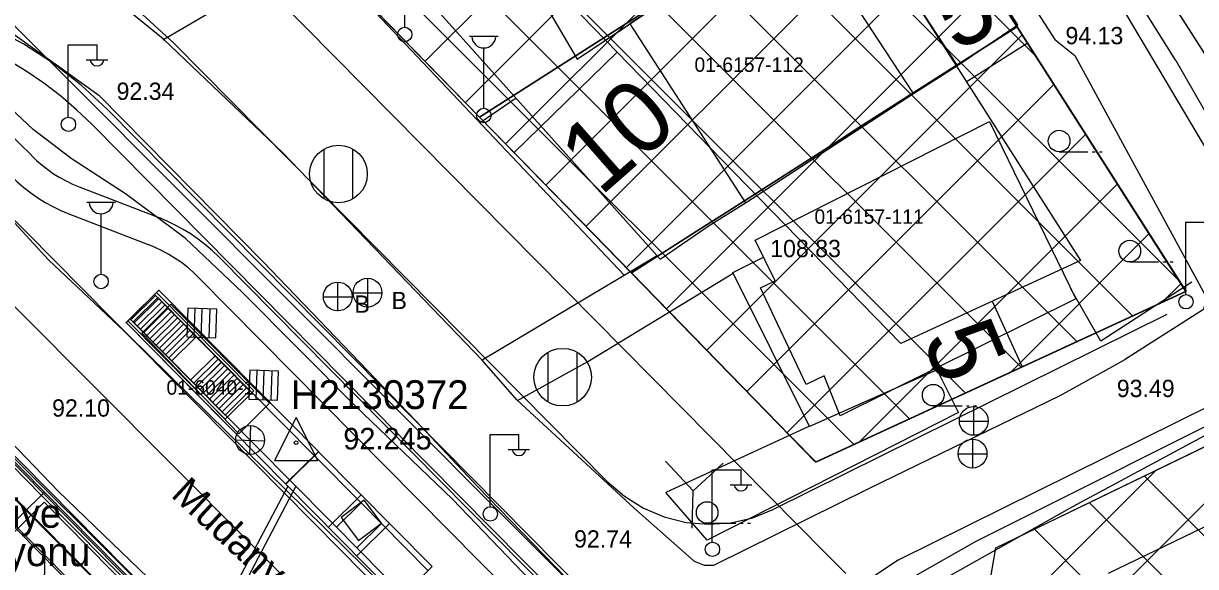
# Model space of a CAD drawing. Extents: x 412225 to 413380, y 4456471 to 4457189.
# Drawn here: x 412847.6 to 412929, y 4456543.1 to 4456580.8 of the extents above; entities that cross this region are included whole.
import ezdxf

# ---------------------------------------------------------------- set-up
doc = ezdxf.new("R2010")
doc.units = 0
for name, color, linetype in [('0_HALİHAZIR', 7, 'Continuous'), ('0_KADASTRO', 7, 'Continuous'), ('Level 20', 7, 'Continuous'), ('Level 28', 7, 'Continuous'), ('Level 34', 7, 'Continuous'), ('Level 62', 7, 'Continuous')]:
    doc.layers.add(name, color=color, linetype=linetype)

msp = doc.modelspace()

# ---------------------------------------------------------------- linework, layer by layer
at = {"layer": '0_HALİHAZIR'}
for p, q in [((412874.076, 4456580.571), (412874.076, 4456584.764)), ((412878.564, 4456579.947), (412880.564, 4456579.947)), ((412850.724, 4456574.359), (412850.724, 4456579.359)), ((412850.724, 4456579.359), (412852.724, 4456579.359)), ((412852.724, 4456578.359), (412852.724, 4456579.359)), ((412879.564, 4456574.947), (412879.564, 4456579.14)), ((412851.964, 4456578.319), (412853.464, 4456578.319)), ((412868.477, 4456568.663), (412868.477, 4456572.123)), ((412870.477, 4456568.663), (412870.477, 4456572.123)), ((412919.494, 4456571.926), (412921.494, 4456571.926)), ((412921.794, 4456571.926), (412921.994, 4456571.926)), ((412922.294, 4456571.926), (412922.494, 4456571.926)), ((412852.002, 4456568.427), (412854.002, 4456568.427)), ((412853.002, 4456563.427), (412853.002, 4456567.62)), ((412928.294, 4456562.045), (412928.294, 4456567.045)), ((412928.294, 4456567.045), (412930.294, 4456567.045)), ((412924.4, 4456564.284), (412926.4, 4456564.284)), ((412926.7, 4456564.284), (412926.9, 4456564.284)), ((412927.2, 4456564.284), (412927.4, 4456564.284)), ((412869.441, 4456560.877), (412869.441, 4456562.877)), ((412871.507, 4456561.146), (412871.507, 4456563.146)), ((412870.487, 4456562.136), (412872.487, 4456562.136)), ((412868.421, 4456561.867), (412870.421, 4456561.867)), ((412859.027, 4456561.084), (412858.959, 4456559.085)), ((412859.027, 4456561.084), (412858.959, 4456559.085)), ((412861.026, 4456561.015), (412859.027, 4456561.084)), ((412861.026, 4456561.015), (412859.027, 4456561.084)), ((412859.463, 4456559.068), (412859.532, 4456561.067)), ((412859.958, 4456559.051), (412860.027, 4456561.05)), ((412860.505, 4456559.032), (412860.574, 4456561.031)), ((412860.957, 4456559.017), (412861.026, 4456561.015)), ((412860.957, 4456559.017), (412861.026, 4456561.015)), ((412858.959, 4456559.085), (412860.957, 4456559.017)), ((412858.959, 4456559.085), (412860.957, 4456559.017)), ((412884.038, 4456554.556), (412884.038, 4456558.016)), ((412886.038, 4456554.556), (412886.038, 4456558.016)), ((412863.325, 4456556.767), (412863.257, 4456554.768)), ((412863.325, 4456556.767), (412863.257, 4456554.768)), ((412865.324, 4456556.698), (412863.325, 4456556.767)), ((412865.324, 4456556.698), (412863.325, 4456556.767)), ((412863.761, 4456554.75), (412863.83, 4456556.749)), ((412864.256, 4456554.733), (412864.325, 4456556.732)), ((412864.804, 4456554.715), (412864.872, 4456556.713)), ((412865.256, 4456554.699), (412865.324, 4456556.698)), ((412865.256, 4456554.699), (412865.324, 4456556.698)), ((412863.257, 4456554.768), (412865.256, 4456554.699)), ((412863.257, 4456554.768), (412865.256, 4456554.699)), ((412910.758, 4456554.288), (412912.758, 4456554.288)), ((412913.058, 4456554.288), (412913.258, 4456554.288)), ((412913.558, 4456554.288), (412913.758, 4456554.288)), ((412913.585, 4456552.241), (412913.585, 4456554.241)), ((412912.565, 4456553.231), (412914.565, 4456553.231)), ((412863.325, 4456550.914), (412863.393, 4456552.913)), ((412880.006, 4456547.316), (412880.006, 4456552.316)), ((412880.006, 4456552.316), (412882.006, 4456552.316)), ((412882.006, 4456551.316), (412882.006, 4456552.316)), ((412862.339, 4456551.938), (412864.338, 4456551.87)), ((412913.505, 4456549.973), (412913.505, 4456551.973)), ((412881.246, 4456551.276), (412882.746, 4456551.276)), ((412912.485, 4456550.963), (412914.485, 4456550.963)), ((412894.105, 4456548.385), (412892.174, 4456550.453)), ((412894.105, 4456548.385), (412896.182, 4456550.315)), ((412895.423, 4456544.861), (412895.423, 4456549.861)), ((412895.423, 4456549.861), (412897.423, 4456549.861)), ((412897.423, 4456548.861), (412897.423, 4456549.861)), ((412894.016, 4456545.797), (412894.105, 4456548.385)), ((412896.663, 4456548.821), (412898.163, 4456548.821)), ((412895.067, 4456546.143), (412897.067, 4456546.143)), ((412897.367, 4456546.143), (412897.567, 4456546.143)), ((412897.867, 4456546.143), (412898.067, 4456546.143)), ((412849.068, 4456543.936), (412849.016, 4456532.158))]:
    msp.add_line(p, q, dxfattribs=at)
for points in [[(412850.036, 4456548.355), (412819.078, 4456580.558), (412809.994, 4456589.718)], [(412881.845, 4456554.722), (412879.45, 4456557.461), (412865.623, 4456571.851), (412857.342, 4456579.74), (412852.222, 4456583.923), (412850.805, 4456584.701), (412849.763, 4456585.251), (412847.518, 4456586.365), (412845.846, 4456586.624), (412840.652, 4456589.088), (412835.581, 4456589.771)], [(412872.443, 4456589.35), (412870.588, 4456588.186), (412891.81, 4456564.468), (412895.209, 4456566.817), (412897.721, 4456568.394), (412909.387, 4456575.969), (412912.447, 4456577.915), (412916.632, 4456580.74), (412911.377, 4456588.906)], [(412879.638, 4456589.268), (412886.04, 4456578.355), (412900.426, 4456588.012), (412899.738, 4456589.039)], [(412879.638, 4456589.268), (412886.04, 4456578.355), (412889.693, 4456580.807), (412897.721, 4456568.394), (412909.387, 4456575.969), (412912.447, 4456577.915), (412906.931, 4456586.341), (412907.561, 4456586.872), (412906.149, 4456588.966)], [(412913.295, 4456588.884), (412919.192, 4456579.735), (412920.588, 4456578.603), (412929.641, 4456561.983), (412929.614, 4456561.425), (412929.522, 4456560.992), (412924.043, 4456557.5)], [(412984.218, 4456588.075), (412978.772, 4456585.262), (412949.513, 4456570.696), (412935.083, 4456563.496), (412934.782, 4456563.569), (412921.975, 4456585.192), (412919.679, 4456588.811)], [(412927.589, 4456578.276), (412921.008, 4456588.796)], [(412857.276, 4456579.702), (412867.714, 4456585.805), (412868.194, 4456586.081), (412870.588, 4456588.186)], [(412867.943, 4456585.937), (412889.326, 4456563.352)], [(412849.345, 4456564.432), (412841.252, 4456573.231), (412832.897, 4456581.857), (412832.65, 4456582.223), (412832.65, 4456582.651), (412833.423, 4456583.292), (412837.875, 4456583.453), (412846.291, 4456580.566), (412852.841, 4456575.869), (412864.259, 4456564.282), (412874.838, 4456553.247), (412879.145, 4456548.669)], [(412890.9, 4456535.18), (412890.351, 4456534.981), (412890.21, 4456534.976), (412885.539, 4456539.337), (412877.386, 4456547.808), (412870.602, 4456554.329), (412862.811, 4456562.153), (412858.84, 4456565.945), (412854.696, 4456569.023), (412850.922, 4456571.464), (412848.287, 4456573.473), (412844.825, 4456576.727), (412840.98, 4456580.4), (412838.838, 4456582.323), (412837.761, 4456583.449)], [(412927.589, 4456578.276), (412932.255, 4456570.172)], [(412881.802, 4456575.653), (412879.304, 4456573.937)], [(412830.527, 4456564.407), (412846.957, 4456547.959), (412869.789, 4456524.873), (412888.463, 4456506.034), (412902.178, 4456491.998), (412914.519, 4456479.375)], [(412933.989, 4456479.153), (412921.628, 4456491.711), (412910.719, 4456502.923), (412900.024, 4456514.208), (412891.297, 4456523.178), (412884.184, 4456530.215), (412875.337, 4456539.124), (412854.962, 4456559.129), (412849.345, 4456564.432)], [(412891.597, 4456564.706), (412879.45, 4456557.461)], [(412912.505, 4456553.836), (412911.034, 4456556.792), (412902.175, 4456552.868), (412896.839, 4456563.561), (412898.98, 4456564.609)], [(412917.143, 4456479.345), (412914.698, 4456481.844), (412896.179, 4456500.83), (412866.951, 4456530.715), (412834.513, 4456563.069)], [(412881.899, 4456554.672), (412886.793, 4456557.381), (412896.872, 4456563.496)], [(412928.699, 4456562.884), (412922.393, 4456558.777)], [(412922.393, 4456558.777), (412920.314, 4456562.428)], [(412881.845, 4456554.722), (412890.003, 4456547.184), (412894.169, 4456543.503), (412894.848, 4456543.244), (412895.527, 4456543.24), (412906.325, 4456548.571), (412919.574, 4456555.025), (412924.043, 4456557.5)], [(412934.553, 4456555.323), (412913.721, 4456544.886), (412901.018, 4456537.65), (412899.925, 4456537.092), (412899.413, 4456536.631), (412899.066, 4456536.044), (412899.079, 4456535.422), (412905.099, 4456524.33), (412906.874, 4456521.045), (412911.663, 4456515.454), (412917.432, 4456509.896), (412918.295, 4456509.22), (412918.942, 4456509.044), (412932.768, 4456516.245)], [(412912.505, 4456553.836), (412895.06, 4456544.98), (412892.189, 4456548.292)], [(412902.164, 4456552.892), (412892.192, 4456548.289)], [(412915.695, 4456515.994), (412905.236, 4456530.767), (412901.401, 4456536.591), (412920.45, 4456547.304), (412930.205, 4456552.551)], [(412919.322, 4456479.321), (412917.621, 4456481.063), (412903.239, 4456495.829), (412894.682, 4456504.249), (412878.07, 4456521.02), (412861.249, 4456537.568), (412850.036, 4456548.355)], [(412938.91, 4456479.097), (412928.702, 4456489.245), (412914.376, 4456504.306), (412903.865, 4456514.655), (412901.031, 4456517.761), (412898.564, 4456521.417), (412892.966, 4456532.024), (412889.877, 4456536.743), (412885.236, 4456542.415), (412879.145, 4456548.669)]]:
    msp.add_lwpolyline(points, dxfattribs=at)
for points in [[(412889.693, 4456580.807), (412897.721, 4456568.394), (412909.387, 4456575.969), (412901.278, 4456588.385), (412900.426, 4456588.012)], [(412914.654, 4456574.037), (412920.66, 4456561.718), (412904.301, 4456553.608), (412903.195, 4456556.369), (412901.942, 4456555.787), (412898.764, 4456562.492), (412899.784, 4456562.98), (412898.393, 4456565.798)], [(412855.833, 4456559.338), (412862.566, 4456552.363), (412864.699, 4456554.484), (412857.847, 4456561.342)], [(412826.614, 4456554.737), (412879.76, 4456501.173), (412885.665, 4456507.019), (412832.527, 4456560.621)], [(412865.038, 4456550.493), (412868.038, 4456550.493), (412866.538, 4456553.493)], [(412869.665, 4456546.536), (412870.875, 4456544.944), (412872.468, 4456546.154), (412871.257, 4456547.747)]]:
    msp.add_lwpolyline(points, close=True, dxfattribs=at)
for centre, radius in [((412874.076, 4456580.071), 0.5), ((412879.564, 4456574.447), 0.5), ((412850.734, 4456573.835), 0.5), ((412919.494, 4456572.676), 0.75), ((412869.477, 4456570.393), 2), ((412924.4, 4456565.034), 0.75), ((412853.002, 4456562.927), 0.5), ((412869.426, 4456561.885), 1), ((412871.492, 4456562.154), 1), ((412928.304, 4456561.52), 0.5), ((412885.038, 4456556.286), 2), ((412910.758, 4456555.038), 0.75), ((412913.57, 4456553.249), 1), ((412863.344, 4456551.922), 1), ((412866.533, 4456551.739), 0.125), ((412913.489, 4456550.981), 1), ((412880.017, 4456546.791), 0.5), ((412895.067, 4456546.893), 0.75), ((412895.433, 4456544.337), 0.5)]:
    msp.add_circle(centre, radius, dxfattribs=at)
for centre, radius, start, end in [((412879.564, 4456579.977), 0.837, 183.298, 356.90719), ((412852.724, 4456578.363), 0.474, 184.83843, 355.14641), ((412853.002, 4456568.457), 0.837, 183.298, 356.90719), ((412882.007, 4456551.319), 0.474, 184.83843, 355.14641), ((412897.423, 4456548.865), 0.474, 184.83843, 355.14641)]:
    msp.add_arc(centre, radius, start, end, dxfattribs=at)
at = {"layer": '0_KADASTRO'}
for points in [[(412867.507, 4456586.399), (412870.513, 4456588.289), (412899.872, 4456606.753), (412908.609, 4456593.073), (412879.275, 4456574.337)], [(412917.33, 4456597.96), (412933.33, 4456606.81), (412953.48, 4456575.26), (412936.96, 4456567.22)], [(412913.93, 4456537.56), (412915.11, 4456544.45), (413017.61, 4456594.11), (413025.23, 4456578.25), (413025.145, 4456578.21), (413017.179, 4456574.027), (413009.477, 4456569.775), (413001.525, 4456565.386), (412993.536, 4456560.975), (412985.532, 4456556.726), (412977.724, 4456552.369), (412969.863, 4456547.982), (412962.005, 4456543.598), (412954.132, 4456539.204), (412945.195, 4456534.457), (412936.308, 4456529.666), (412926.813, 4456524.527)], [(412879.275, 4456574.337), (412908.609, 4456593.073), (412916.574, 4456580.611), (412916.175, 4456580.357), (412905.604, 4456573.61), (412904.319, 4456572.79), (412896.563, 4456567.84), (412894.881, 4456566.767), (412889.808, 4456563.529), (412887.18, 4456566.226)], [(412831.32, 4456576.91), (412843.23, 4456584.47), (412896.33, 4456531.19), (412884.4, 4456523.61)], [(412889.808, 4456563.529), (412894.881, 4456566.767), (412896.563, 4456567.84), (412904.319, 4456572.79), (412905.604, 4456573.61), (412916.175, 4456580.357), (412916.574, 4456580.611), (412928.32, 4456562.23), (412928.26, 4456562.202), (412902.627, 4456550.378), (412900.836, 4456552.215), (412892.47, 4456560.798)]]:
    msp.add_lwpolyline(points, close=True, dxfattribs=at)
at = {"layer": 'Level 20'}
for p, q in [((412913.053, 4456576.782), (412917.267, 4456579.474)), ((412888.822, 4456578.844), (412881.659, 4456571.866)), ((412922.93, 4456542.682), (412973.194, 4456567.036)), ((412920.976, 4456564.381), (412908.513, 4456558.634)), ((412914.845, 4456561.553), (412916.939, 4456557.013))]:
    msp.add_line(p, q, dxfattribs=at)
for points in [[(412867.035, 4456648.833), (412887.632, 4456616.591), (412890.181, 4456612.594), (412904.356, 4456590.395), (412912.32, 4456577.931), (412920.976, 4456564.381)], [(412908.513, 4456558.634), (412896.927, 4456570.522), (412886.396, 4456581.334), (412864.245, 4456604.044), (412838.252, 4456630.718)]]:
    msp.add_lwpolyline(points, dxfattribs=at)
at = {"layer": 'Level 28'}
for p, q in [((412936.958, 4456567.223), (412917.331, 4456597.957)), ((412915.108, 4456544.448), (413017.607, 4456594.111)), ((412928.276, 4456562.241), (412902.582, 4456550.392)), ((412913.926, 4456537.564), (412915.108, 4456544.448))]:
    msp.add_line(p, q, dxfattribs=at)
for points in [[(412871.266, 4456651.496), (412891.846, 4456619.281), (412894.396, 4456615.284), (412908.57, 4456593.086), (412916.533, 4456580.623), (412928.276, 4456562.241)], [(412902.582, 4456550.392), (412889.765, 4456563.544), (412879.235, 4456574.354), (412857.085, 4456597.063), (412829.598, 4456625.27)]]:
    msp.add_lwpolyline(points, dxfattribs=at)
at = {"layer": 'Level 34'}
for p, q in [((412917.768, 4456578.69), (412855.122, 4456641.335)), ((412927.774, 4456563.027), (412851.651, 4456639.15)), ((412924.599, 4456560.545), (412848.179, 4456636.965)), ((412920.727, 4456558.76), (412844.707, 4456634.78)), ((412916.856, 4456556.974), (412841.236, 4456632.595)), ((412912.984, 4456555.189), (412837.763, 4456630.41)), ((412909.113, 4456553.404), (412834.291, 4456628.225)), ((412905.241, 4456551.618), (412830.82, 4456626.04)), ((412875.482, 4456578.202), (412901.476, 4456604.196)), ((412878.275, 4456575.338), (412903.68, 4456600.744)), ((412881.067, 4456572.474), (412905.885, 4456597.292)), ((412883.858, 4456569.608), (412908.089, 4456593.839)), ((412886.649, 4456566.742), (412910.294, 4456590.387)), ((412889.441, 4456563.877), (412912.5, 4456586.936)), ((412892.233, 4456561.012), (412914.705, 4456583.484)), ((412895.024, 4456558.147), (412916.91, 4456580.033)), ((412897.816, 4456555.282), (412919.115, 4456576.581)), ((412900.608, 4456552.417), (412921.32, 4456573.129)), ((412905.659, 4456551.811), (412923.525, 4456569.677)), ((412916.157, 4456556.652), (412925.73, 4456566.226)), ((412926.655, 4456561.494), (412927.936, 4456562.774)), ((412916.753, 4456534.704), (412937.201, 4456555.152)), ((412913.941, 4456537.55), (412926.227, 4456549.835)), ((412925.398, 4456549.434), (412996.347, 4456478.484)), ((412921.587, 4456547.587), (412990.624, 4456478.551)), ((412917.777, 4456545.741), (412984.901, 4456478.617))]:
    msp.add_line(p, q, dxfattribs=at)
at = {"layer": 'Level 62'}
for p, q in [((412903.338, 4456544.013), (412825.552, 4456622.724)), ((412861.157, 4456535.93), (412814.897, 4456582.691)), ((412861.441, 4456536.212), (412815.182, 4456582.973)), ((412813.318, 4456581.879), (412906.152, 4456488.04)), ((412869.617, 4456544.3), (412834.498, 4456579.799)), ((412888.137, 4456549.04), (412858.038, 4456579.465)), ((412817.306, 4456575.893), (412900.939, 4456491.323)), ((412876.726, 4456551.333), (412853.418, 4456574.893)), ((412875.66, 4456550.278), (412852.351, 4456573.838)), ((412851.483, 4456569.497), (412856.998, 4456567.359)), ((412850.76, 4456567.632), (412856.276, 4456565.495)), ((412889.835, 4456535.657), (412861.193, 4456564.61)), ((412888.413, 4456534.251), (412859.771, 4456563.203)), ((412854.707, 4456560.045), (412856.982, 4456562.296)), ((412857.007, 4456562.321), (412854.732, 4456560.07)), ((412855.016, 4456560.351), (412857.007, 4456562.321)), ((412855.062, 4456560.256), (412856.768, 4456561.944)), ((412855.062, 4456560.256), (412856.768, 4456561.944)), ((412856.698, 4456562.015), (412863.309, 4456555.332)), ((412856.698, 4456562.015), (412863.309, 4456555.332)), ((412856.84, 4456562.155), (412863.592, 4456555.331)), ((412856.84, 4456562.155), (412863.591, 4456555.331)), ((412857.007, 4456562.321), (412863.758, 4456555.496)), ((412868.084, 4456551.124), (412857.007, 4456562.321)), ((412835.554, 4456561.549), (412848.85, 4456548.104)), ((412835.767, 4456561.76), (412849.063, 4456548.315)), ((412856.934, 4456561.826), (412855.227, 4456560.138)), ((412855.227, 4456560.138), (412856.934, 4456561.826)), ((412855.28, 4456560.035), (412856.986, 4456561.723)), ((412855.28, 4456560.035), (412856.986, 4456561.723)), ((412855.498, 4456559.815), (412857.204, 4456561.503)), ((412855.498, 4456559.815), (412857.204, 4456561.503)), ((412855.716, 4456559.595), (412857.422, 4456561.283)), ((412855.716, 4456559.595), (412857.422, 4456561.282)), ((412856.934, 4456561.826), (412867.79, 4456550.851)), ((412854.732, 4456560.07), (412855.016, 4456560.351)), ((412854.992, 4456560.327), (412861.603, 4456553.644)), ((412854.992, 4456560.327), (412861.602, 4456553.644)), ((412855.934, 4456559.374), (412857.64, 4456561.062)), ((412855.934, 4456559.374), (412857.64, 4456561.062)), ((412856.152, 4456559.154), (412857.858, 4456560.842)), ((412856.152, 4456559.154), (412857.858, 4456560.842)), ((412856.37, 4456558.934), (412858.076, 4456560.621)), ((412856.37, 4456558.933), (412858.076, 4456560.621)), ((412856.588, 4456558.713), (412858.294, 4456560.401)), ((412856.588, 4456558.713), (412858.294, 4456560.401)), ((412926.977, 4456560.642), (412899.688, 4456547.114)), ((412854.732, 4456560.07), (412861.483, 4456553.245)), ((412865.809, 4456548.873), (412854.732, 4456560.07)), ((412854.849, 4456560.186), (412861.601, 4456553.362)), ((412854.849, 4456560.186), (412861.601, 4456553.361)), ((412855.227, 4456560.138), (412866.084, 4456549.163)), ((412856.806, 4456558.493), (412858.512, 4456560.181)), ((412856.806, 4456558.493), (412858.512, 4456560.181)), ((412857.024, 4456558.272), (412858.73, 4456559.96)), ((412857.024, 4456558.272), (412858.73, 4456559.96)), ((412857.242, 4456558.052), (412858.948, 4456559.74)), ((412857.242, 4456558.052), (412858.948, 4456559.74)), ((412857.46, 4456557.832), (412859.166, 4456559.52)), ((412857.46, 4456557.831), (412859.166, 4456559.519)), ((412857.678, 4456557.611), (412859.384, 4456559.299)), ((412857.678, 4456557.611), (412859.384, 4456559.299)), ((412857.896, 4456557.391), (412859.602, 4456559.079)), ((412857.896, 4456557.391), (412859.602, 4456559.079)), ((412859.204, 4456556.069), (412860.91, 4456557.756)), ((412859.204, 4456556.068), (412860.911, 4456557.756)), ((412859.422, 4456555.848), (412861.128, 4456557.536)), ((412859.422, 4456555.848), (412861.129, 4456557.536)), ((412859.64, 4456555.628), (412861.347, 4456557.316)), ((412859.64, 4456555.628), (412861.346, 4456557.316)), ((412859.858, 4456555.407), (412861.565, 4456557.095)), ((412859.858, 4456555.407), (412861.564, 4456557.095)), ((412860.076, 4456555.187), (412861.783, 4456556.875)), ((412860.076, 4456555.187), (412861.783, 4456556.875)), ((412860.294, 4456554.967), (412862.001, 4456556.655)), ((412860.294, 4456554.967), (412862.001, 4456556.654)), ((412860.512, 4456554.746), (412862.219, 4456556.434)), ((412860.512, 4456554.746), (412862.219, 4456556.434)), ((412860.73, 4456554.526), (412862.437, 4456556.214)), ((412860.73, 4456554.526), (412862.437, 4456556.214)), ((412860.948, 4456554.306), (412862.655, 4456555.993)), ((412860.949, 4456554.305), (412862.655, 4456555.993)), ((412861.166, 4456554.085), (412862.873, 4456555.773)), ((412861.167, 4456554.085), (412862.873, 4456555.773)), ((412861.384, 4456553.865), (412863.091, 4456555.553)), ((412861.385, 4456553.865), (412863.091, 4456555.553)), ((412861.601, 4456553.362), (412863.591, 4456555.331)), ((412861.601, 4456553.361), (412863.592, 4456555.331)), ((412861.602, 4456553.644), (412863.309, 4456555.332)), ((412861.603, 4456553.644), (412863.309, 4456555.332)), ((412930.086, 4456554.371), (412908.327, 4456543.583)), ((412868.084, 4456551.124), (412865.809, 4456548.873)), ((412868.098, 4456551.11), (412865.823, 4456548.859)), ((412871.049, 4456547.558), (412867.813, 4456550.828)), ((412875.975, 4456543.147), (412868.098, 4456551.11)), ((412876.726, 4456551.333), (412948.244, 4456479.04)), ((412875.66, 4456550.278), (412946.11, 4456479.065)), ((412866.107, 4456549.14), (412869.061, 4456546.155)), ((412866.528, 4456548.715), (412866.107, 4456549.14)), ((412849.063, 4456548.315), (412845.291, 4456544.583)), ((412848.85, 4456548.104), (412872.758, 4456523.929)), ((412849.063, 4456548.315), (412872.971, 4456524.14)), ((412865.964, 4456548.717), (412862.549, 4456542.244)), ((412866.528, 4456548.715), (412862.955, 4456541.943)), ((412865.964, 4456548.717), (412865.823, 4456548.859)), ((412865.823, 4456548.859), (412873.559, 4456541.039)), ((412871.052, 4456548.124), (412868.777, 4456545.873)), ((412849.054, 4456547.601), (412845.643, 4456544.227)), ((412849.054, 4456547.601), (412858.759, 4456537.791)), ((412871.049, 4456547.558), (412869.342, 4456545.87)), ((412871.049, 4456547.558), (412872.455, 4456546.136)), ((412869.061, 4456546.155), (412871.03, 4456544.164)), ((412873.021, 4456546.133), (412870.746, 4456543.883)), ((412872.455, 4456546.136), (412870.749, 4456544.448)), ((412875.69, 4456542.866), (412872.455, 4456546.136)), ((412869.617, 4456544.3), (412934.015, 4456479.205)), ((412871.03, 4456544.164), (412873.984, 4456541.178)), ((412903.338, 4456544.013), (412903.338, 4456544.013)), ((412904.682, 4456542.653), (412903.338, 4456544.013)), ((412875.975, 4456543.147), (412873.7, 4456540.897))]:
    msp.add_line(p, q, dxfattribs=at)
for points in [[(412858.038, 4456579.465), (412855.854, 4456581.492), (412853.505, 4456583.327), (412851.008, 4456584.955), (412848.382, 4456586.365), (412845.646, 4456587.546), (412842.819, 4456588.49), (412839.922, 4456589.19), (412836.975, 4456589.641)], [(412853.418, 4456574.893), (412851.626, 4456576.556), (412849.698, 4456578.058), (412847.648, 4456579.39), (412845.492, 4456580.542), (412843.246, 4456581.504), (412840.925, 4456582.271), (412838.546, 4456582.835), (412836.129, 4456583.194)], [(412852.351, 4456573.838), (412851.293, 4456574.852), (412850.181, 4456575.806), (412849.019, 4456576.699), (412847.81, 4456577.527), (412846.558, 4456578.289), (412845.267, 4456578.981), (412843.94, 4456579.603), (412842.581, 4456580.151)], [(412841.505, 4456578.529), (412842.325, 4456577.662), (412843.148, 4456576.798), (412843.976, 4456575.937), (412844.806, 4456575.08), (412845.64, 4456574.227), (412846.478, 4456573.376), (412847.319, 4456572.529), (412848.163, 4456571.686)], [(412848.162, 4456571.674), (412848.523, 4456571.328), (412848.902, 4456571.001), (412849.297, 4456570.695), (412849.708, 4456570.41), (412850.133, 4456570.147), (412850.571, 4456569.907), (412851.022, 4456569.69), (412851.483, 4456569.497)], [(412846.74, 4456570.267), (412847.177, 4456569.848), (412847.636, 4456569.453), (412848.114, 4456569.082), (412848.611, 4456568.737), (412849.126, 4456568.419), (412849.657, 4456568.128), (412850.202, 4456567.866), (412850.76, 4456567.632)], [(412861.193, 4456564.61), (412860.737, 4456565.047), (412860.259, 4456565.459), (412859.76, 4456565.846), (412859.241, 4456566.206), (412858.704, 4456566.538), (412858.15, 4456566.842), (412857.581, 4456567.116), (412856.998, 4456567.359)], [(412859.771, 4456563.203), (412859.391, 4456563.568), (412858.993, 4456563.911), (412858.577, 4456564.234), (412858.144, 4456564.534), (412857.697, 4456564.81), (412857.235, 4456565.063), (412856.761, 4456565.292), (412856.276, 4456565.495)], [(412888.137, 4456549.04), (412889.319, 4456548.019), (412890.646, 4456547.194), (412892.085, 4456546.586), (412893.601, 4456546.209), (412895.157, 4456546.073), (412896.716, 4456546.182), (412898.238, 4456546.531), (412899.688, 4456547.114)], [(412908.327, 4456543.583), (412906.747, 4456542.552), (412905.453, 4456541.18), (412904.517, 4456539.543), (412903.989, 4456537.732), (412903.9, 4456535.848), (412904.255, 4456533.995), (412905.034, 4456532.277), (412906.193, 4456530.789)]]:
    msp.add_lwpolyline(points, dxfattribs=at)

# ---------------------------------------------------------------- texts
at = {"layer": '0_HALİHAZIR'}
for s, height, p in [('94.13', 1.2, (412919.936, 4456579.393)), ('92.34', 1.2, (412854.077, 4456575.535)), ('108.83', 1.2, (412899.442, 4456564.617)), ('B', 1.2, (412870.578, 4456560.76)), ('B', 1.2, (412873.157, 4456561.009)), ('H2130372', 2, (412866.163, 4456554.073)), ('93.49', 1.2, (412923.498, 4456554.905)), ('92.10', 1.2, (412849.6, 4456553.547)), ('92.245', 1.5, (412869.812, 4456551.266)), ('Hamitler Fethiye ', 2, (412830.767, 4456545.831)), ('Metro Ýsyasyonu', 2, (412831.587, 4456543.169)), ('92.74', 1.2, (412885.827, 4456544.457))]:
    msp.add_text(s, height=height, dxfattribs=at).set_placement(p)
msp.add_text('Mudanya', height=2, rotation=317.1344, dxfattribs=at).set_placement((412857.777, 4456548.038))
at = {"layer": '0_KADASTRO'}
for s, p in [('01-6157-112', (412894.188, 4456577.479)), ('01-6157-112', (412894.188, 4456577.479)), ('01-6157-111', (412902.514, 4456566.932)), ('01-6157-111', (412902.514, 4456566.932)), ('01-6040-1', (412857.54, 4456555.069)), ('01-6040-1', (412857.54, 4456555.069))]:
    msp.add_text(s, height=1, dxfattribs=at).set_placement(p)
at = {"layer": 'Level 20'}
for s, rotation, p in [('5', 28.84139, (412912.331, 4456578.791)), ('10', 41.29978, (412887.649, 4456568.774)), ('5', 292.83191, (412909.946, 4456558.926))]:
    msp.add_text(s, height=5, rotation=rotation, dxfattribs=at).set_placement(p)

doc.saveas('drawing.dxf')
